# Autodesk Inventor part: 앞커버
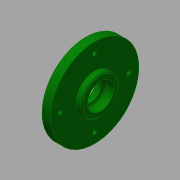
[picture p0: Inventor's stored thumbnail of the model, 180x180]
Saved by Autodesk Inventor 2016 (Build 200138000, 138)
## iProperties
Created: 2015-09
Part Number: 앞커버
Material: 알루미늄 6061
Document SubType Name: Modeling
Designer: mduedu
Density: 2.71 g/cm^3
Mass: 58.9874 g
Surface Area: 98.7754 cm^2
Volume: 21.7666 cm^3
Appearance: 진녹색
Author: mduedu
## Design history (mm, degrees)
sketch "스케치1"
  geometry: L1 (-6.5, 63)-(-11.5, 63); L2 (-11.5, 63)-(-11.5, 84.5); L3 (-11.5, 84.5)-(-19.5, 84.5); L4 (-19.5, 84.5)-(-19.5, 70.5); L5 (-24.5, 70.5)-(-24.5, 54.5); L6 (-24.5, 54.5)-(-6.5, 54.5); L7 (-6.5, 54.5)-(-6.5, 63); L8 (-79.5, 39.5)-(-79.5, 54.5) reference; L9 (48.5, 54.5)-(48.5, 39.5) reference; L10 (-79.5, 47)-(48.5, 47); L11 (-19.5, 70.5)-(-24.5, 70.5); 3 further points
  constraints: 18 end point, 6 parallel, 4 midpoint, 1 horizontal, 1 perpendicular, 1 vertical alignment
  dimensions: "d0" = 18 distance between parallel lines of L7 L5; "d3" = 32 diameter of L1 L10; "d5" = 5 distance of L1.start L1.end; "d6" = 75 diameter of L3 L10; "d7" = 8 distance of L2.end L3.end; "d8" = 47 diameter of L4.end L10; "d61" = 15 diameter of L6 L10
revolve "회전1" sketch "스케치1" stored, may be unused: angle "d4" = 90 deg
sketch "스케치2"
  geometry: C1 r 37.5 at (0, 0) reference; 2 further points
  constraints: 1 coincident
hole "구멍1" sketch "스케치2" at (0, 0) diameter "d11" = 22; stored, may be unused: countersink angle "d15" = 90 deg, drill point angle "d17" = 0 deg; dims "d12" = 6, "d13" = 4, "d14" = 2, "d16" = 8
fillet "모깎기1" dims "d18" = 3
fillet "모깎기2" dims "d19" = 1
sketch "스케치3"
  geometry: C1 r 37.5 at (0, 0) reference; 2 further points
  constraints: 1 coincident
hole "구멍2" sketch "스케치3" at (0, 0) diameter "d20" = 30; stored, may be unused: countersink angle "d24" = 90 deg, drill point angle "d26" = 0 deg; dims "d21" = 6, "d22" = 4, "d23" = 2, "d25" = 7.5
fillet "모깎기3" dims "d27" = 0.3
chamfer "모따기1" distance "d28" = 1; stored, may be unused: second distance "d29" = 2, angle "d30" = 30 deg
sketch "스케치7" dims "d56" = 58
  geometry: C1 r 37.5 at (0, 0) reference; 5 further points
  constraints: 2 vertical alignment, 1 coincident, 7 other
  dimensions: "d59" = 360 deg dimension on C1.centre point (0, 29) (derived)
hole "구멍4" sketch "스케치7" at (0, 29), (-29, 0), (0, -29), (29, 0) diameter "d48" = 3.4; stored, may be unused: countersink angle "d52" = 90 deg, drill point angle "d54" = 0 deg; dims "d49" = 6, "d50" = 6.5, "d51" = 3.4, "d53" = 8
hole "구멍5" diameter "d64" = 17; stored, may be unused: countersink angle "d68" = 90 deg, drill point angle "d70" = 118 deg; dims "d62" = 10, "d63" = 10, "d65" = 6, "d66" = 4, "d67" = 2, "d69" = 8
chamfer "모따기2" distance "d71" = 1; stored, may be unused: second distance "d72" = 2, angle "d73" = 45 deg
node "솔리드1"
node "참조1"
node "참조2"
